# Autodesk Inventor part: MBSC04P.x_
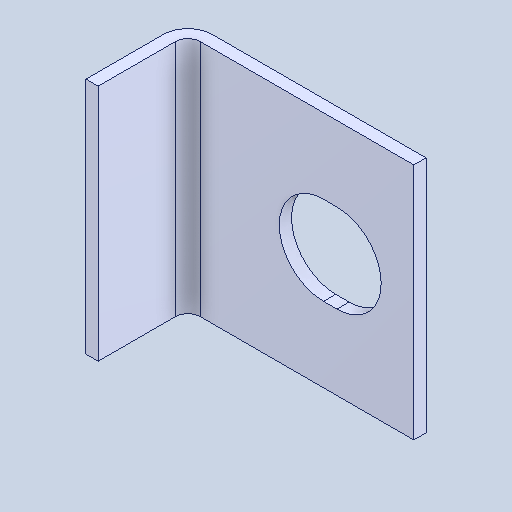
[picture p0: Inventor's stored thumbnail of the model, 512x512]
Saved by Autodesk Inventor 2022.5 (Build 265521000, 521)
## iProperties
Created: 2024-05
Part Number: MBSC04P.x_
Material: 一般
Document SubType Name: Modeling
Designer: ImaoCorp
Density: 1 g/cm^3
Appearance: 既定
Author: ImaoCorp
Sending System: SOLIDWORKS 2022-2022290
MC: AMD64
MC_MODEL: Intel64 Family 6 Model 60 Stepping 3, GenuineIntel
OS: Windows_NT
FRU: Parasolid Version 33.1, build 260,  4-25-2022
FORMAT: text
GUISE: transmit
KEY: FILEMBSC04P.x_t
DATE: Mon May 20 16:27:43 2024
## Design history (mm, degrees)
feature "Base1"
node "ソリッド1"
